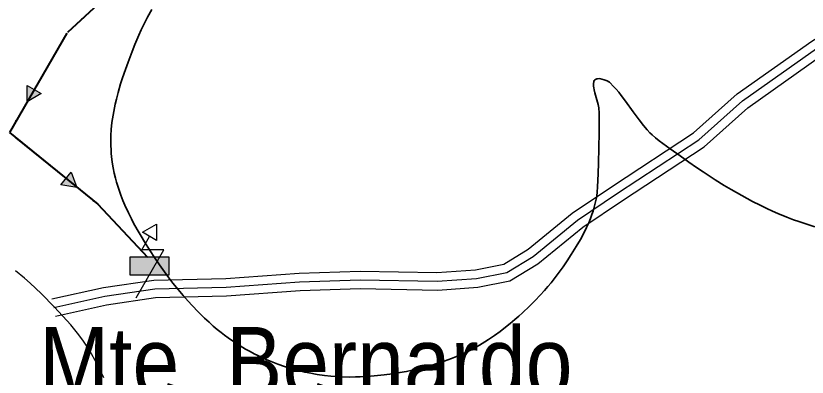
# Model space of a CAD drawing. Extents: x -64005 to -55000, y -89025 to -80000.
# Drawn here: x -61726 to -60821, y -88023 to -87610 of the extents above; entities that cross this region are included whole.
import ezdxf
from ezdxf.enums import TextEntityAlignment as Align

# ---------------------------------------------------------------- set-up
doc = ezdxf.new("R2010")
doc.units = 0
doc.header["$LTSCALE"] = 32
doc.linetypes.add('DOT_DASHED', pattern=[7.7, 5, -1.2, 0.3, -1.2])
doc.linetypes.add('LONG_DASHED', pattern=[7.5, 6, -1.5])
for name, color, linetype, lineweight in [('18', 7, 'Continuous', 25), ('24', 7, 'Continuous', 25), ('25', 7, 'Continuous', 35), ('39', 7, 'LONG_DASHED', 25), ('8', 7, 'Continuous', 25)]:
    doc.layers.add(name, color=color, linetype=linetype, lineweight=lineweight)
doc.layers.add('45', color=7, linetype='Continuous')

msp = doc.modelspace()

# ---------------------------------------------------------------- hatches: boundary and pattern name
at = {"layer": '18'}
for points in [[(-61696.9, -87699.17), (-61712.91, -87708.43), (-61712.93, -87689.93)], [(-61662.62, -87789.01), (-61656.02, -87806.29), (-61674.29, -87803.37)], [(-61595.69, -87906.11), (-61550.69, -87906.11), (-61550.69, -87886.11), (-61595.69, -87886.11)]]:
    msp.add_hatch(color=256, dxfattribs=at).paths.add_polyline_path(points)

# ---------------------------------------------------------------- linework, layer by layer
for p, q in [((-61667.98, -87630.44), (-61704.91, -87694.55)), ((-61725.87, -87749.53), (-61668.45, -87796.19)), ((-61618.97, -87839.71), (-61575.33, -87886.11))]:
    msp.add_line(p, q, dxfattribs=at)
at = {"layer": '18', "linetype": 'DOT_DASHED', "lineweight": 40}
msp.add_lwpolyline([(-62031.28, -86290.37), (-61300.5, -86486.3), (-61179.73, -86532.12), (-61069.18, -86626.02), (-60966.6, -86696.29), (-60858.8, -86771.78), (-60980.4, -86988.93), (-61117.47, -87235.6), (-61208.88, -87325.91), (-61262.1, -87419.12), (-61406.49, -87469.74), (-61549.57, -87520.74), (-61667.76, -87630.06), (-61733.17, -87743.6), (-61632.21, -87825.64), (-61575.32, -87886.11)], dxfattribs=at)
at = {"layer": '18'}
for points in [[(-61696.9, -87699.17), (-61712.91, -87708.43), (-61712.93, -87689.93)], [(-61662.62, -87789.01), (-61656.02, -87806.29), (-61674.29, -87803.37)], [(-61580.93, -87857.62), (-61564.91, -87848.36), (-61564.91, -87866.86)], [(-61595.69, -87906.11), (-61550.69, -87906.11), (-61550.69, -87886.11), (-61595.69, -87886.11)]]:
    msp.add_lwpolyline(points, close=True, dxfattribs=at)
msp.add_lwpolyline([(-61588.49, -87932.61), (-61556.8, -87877.61), (-61581.8, -87877.61), (-61572.92, -87862.24)], dxfattribs=at)
for centre in [(-61649.73, -87613.39), (-61725.39, -87730.09), (-61636.62, -87822.06)]:
    msp.add_circle(centre, 0.5, dxfattribs=at)
at = {"layer": '24'}
msp.add_lwpolyline([(-61625.47, -88023.89), (-61627.38, -88019.47), (-61633.41, -88007.54), (-61641.49, -87993.19), (-61649.48, -87980.82), (-61655.27, -87972.87), (-61663.12, -87963.26), (-61681.59, -87943.06), (-61696.95, -87927.52), (-61709.57, -87915.68), (-61716.11, -87910.02), (-61726.49, -87901.79)], dxfattribs=at)
at = {"layer": '25'}
for points in [[(-61587.11, -87854.54), (-61591.23, -87847.13), (-61593.85, -87842.16), (-61597.18, -87835.51), (-61601.3, -87826.55), (-61603.5, -87821.36), (-61605.84, -87815.36), (-61608.31, -87808.4), (-61610.84, -87800.28), (-61612.05, -87795.88), (-61613.49, -87789.94), (-61614.69, -87783.96), (-61615.37, -87779.95), (-61616.11, -87774.59), (-61616.83, -87767.41), (-61617.1, -87763.31), (-61617.29, -87758.62), (-61617.34, -87753.26), (-61617.2, -87747.15), (-61616.79, -87740.19), (-61615.98, -87732.31), (-61615.4, -87728.13), (-61613.97, -87719.6), (-61612.25, -87711.11), (-61610.94, -87705.47), (-61609, -87697.98), (-61606.09, -87688.02), (-61604.26, -87682.34), (-61602.03, -87675.86), (-61597.53, -87663.36), (-61592.91, -87651.05), (-61589.71, -87642.94), (-61585.23, -87632.26), (-61582.53, -87626.23), (-61579.3, -87619.41), (-61575.39, -87611.69), (-61570.61, -87602.99)], [(-61053.06, -87683.28), (-61055.75, -87682.52), (-61057.28, -87682.24), (-61058.96, -87682.08), (-61060.74, -87682.13), (-61061.61, -87682.28), (-61062.45, -87682.53), (-61063.24, -87682.91), (-61063.95, -87683.45), (-61064.52, -87684.2), (-61064.89, -87685.2), (-61065.28, -87687.93), (-61065.31, -87690.66), (-61065.16, -87692.5), (-61064.78, -87694.95), (-61064.03, -87698.23), (-61060.14, -87711.47), (-61059.38, -87715.28), (-61059.13, -87717.32), (-61059.03, -87719.49), (-61058.99, -87731.62), (-61059.03, -87743.75), (-61059.24, -87761.27), (-61059.61, -87778.8), (-61059.99, -87790.48), (-61060.69, -87806.06), (-61061.1, -87811.26), (-61061.78, -87816.41), (-61062.38, -87819.81), (-61063.34, -87824.31), (-61064.9, -87830.24), (-61065.93, -87833.61), (-61067.22, -87837.42), (-61068.84, -87841.75), (-61070.86, -87846.67), (-61073.38, -87852.23), (-61076.5, -87858.54), (-61080.36, -87865.7), (-61085.07, -87873.81), (-61090.77, -87883.01), (-61095.46, -87890.19), (-61100.25, -87897.15), (-61103.51, -87901.68), (-61107.93, -87907.58), (-61113.97, -87915.21), (-61117.5, -87919.45), (-61121.61, -87924.21), (-61126.41, -87929.54), (-61132.04, -87935.48), (-61138.66, -87942.09), (-61146.5, -87949.46), (-61150.8, -87953.3), (-61155.48, -87957.35), (-61160.59, -87961.61), (-61166.17, -87966.1), (-61172.27, -87970.83), (-61178.78, -87975.61), (-61185.33, -87980.08), (-61189.73, -87982.9), (-61195.66, -87986.47), (-61203.72, -87990.92)], [(-60812.39, -87851.2), (-60821.64, -87848.44), (-60830.69, -87845.45), (-60836.63, -87843.32), (-60844.46, -87840.33), (-60854.76, -87836.05), (-60860.59, -87833.47), (-60867.23, -87830.4), (-60874.8, -87826.73), (-60883.45, -87822.35), (-60895.79, -87815.72), (-60907.89, -87808.81), (-60915.83, -87804.06), (-60926.27, -87797.56), (-60939.98, -87788.63), (-60947.71, -87783.42), (-60956.48, -87777.38), (-60966.41, -87770.38), (-60977.68, -87762.28), (-60990.47, -87752.94), (-60994.54, -87749.74), (-60998.4, -87746.28), (-61000.87, -87743.84), (-61004.06, -87740.46), (-61008.14, -87735.74), (-61013.33, -87729.15), (-61019.97, -87720.07), (-61028.65, -87707.9), (-61033.7, -87701.17), (-61036.46, -87697.71), (-61039.48, -87694.15), (-61042.81, -87690.52), (-61046.5, -87686.87), (-61047.17, -87686.3), (-61047.95, -87685.74), (-61049.76, -87684.68), (-61051.12, -87684.03), (-61053.06, -87683.28)], [(-61203.72, -87990.92), (-61208.42, -87993.31), (-61213.9, -87995.91), (-61220.31, -87998.74), (-61227.86, -88001.78), (-61236.14, -88004.82), (-61244.44, -88007.59), (-61249.98, -88009.29), (-61257.38, -88011.37), (-61267.26, -88013.85), (-61272.91, -88015.13), (-61279.38, -88016.45), (-61286.78, -88017.81), (-61295.26, -88019.17), (-61304.96, -88020.47), (-61316.06, -88021.67), (-61324.05, -88022.3), (-61332.07, -88022.72), (-61337.44, -88022.87), (-61344.61, -88022.9), (-61354.19, -88022.64), (-61359.67, -88022.34), (-61365.93, -88021.84), (-61373.1, -88021.08), (-61381.28, -88019.94), (-61390.62, -88018.29), (-61395.6, -88017.25), (-61400.89, -88016.02), (-61406.53, -88014.56), (-61412.52, -88012.84), (-61418.9, -88010.81), (-61426.51, -88008.13), (-61433.95, -88005.25), (-61438.81, -88003.22), (-61445.18, -88000.37), (-61453.48, -87996.31), (-61458.13, -87993.85), (-61463.37, -87990.92), (-61469.26, -87987.41), (-61475.86, -87983.17), (-61483.26, -87978.03), (-61487.15, -87975.16), (-61491.25, -87971.99), (-61495.57, -87968.5), (-61500.14, -87964.64), (-61504.95, -87960.36), (-61510.03, -87955.62), (-61517.35, -87948.42), (-61524.36, -87941.15), (-61528.87, -87936.27), (-61534.7, -87929.69), (-61542.16, -87920.81), (-61546.28, -87915.66), (-61550.88, -87909.71), (-61556.01, -87902.81), (-61561.71, -87894.79), (-61568.05, -87885.43), (-61575.13, -87874.44), (-61578.85, -87868.45), (-61582.78, -87861.95), (-61587.11, -87854.54)]]:
    msp.add_lwpolyline(points, dxfattribs=at)
at = {"layer": '39'}
msp.add_lwpolyline([(-61682.66, -87943.49), (-61624.01, -87930.45), (-61567.15, -87922.15), (-61485.4, -87920.36), (-61401.54, -87914.21), (-61332.23, -87911.83), (-61243.98, -87913.59), (-61199.1, -87910.35), (-61164.6, -87903.51), (-61134.57, -87885.35), (-61083.65, -87843.86), (-61038.04, -87813.03), (-60945.03, -87751.99), (-60894.96, -87707.29), (-60810.36, -87647.49), (-60702.44, -87581.03), (-60641.06, -87527.36), (-60578.51, -87467.48), (-60546.87, -87444.97), (-60520.46, -87425.15)], dxfattribs=at)
at = {"layer": '8', "linetype": 'LONG_DASHED'}
msp.add_lwpolyline([(-61684.83, -87933.73), (-61625.82, -87920.61), (-61567.98, -87912.17), (-61485.87, -87910.37), (-61402.08, -87904.22), (-61332.3, -87901.83), (-61244.51, -87903.58), (-61200.44, -87900.42), (-61167.96, -87893.86), (-61140.17, -87877.05), (-61089.63, -87835.82), (-61043.79, -87804.84), (-60951.14, -87744.04), (-60901.06, -87699.33), (-60815.87, -87639.14), (-60708.5, -87573.05), (-60647.63, -87519.82), (-60584.9, -87459.75), (-60553.22, -87437.23), (-60532.74, -87421.86)], dxfattribs=at)
at = {"layer": '8'}
msp.add_lwpolyline([(-61680.49, -87953.25), (-61622.2, -87940.29), (-61566.32, -87932.13), (-61484.93, -87930.35), (-61401, -87924.2), (-61332.16, -87921.83), (-61243.45, -87923.6), (-61197.76, -87920.28), (-61161.24, -87913.16), (-61128.97, -87893.65), (-61077.68, -87851.9), (-61032.29, -87821.22), (-60938.92, -87759.94), (-60888.86, -87715.25), (-60804.85, -87655.84), (-60696.38, -87589.01), (-60634.49, -87534.9), (-60572.12, -87475.21), (-60540.52, -87452.71), (-60526.59, -87442.26)], dxfattribs=at)

# ---------------------------------------------------------------- texts
at = {"layer": '45', "width": 0.9}
msp.add_text('Mte. Bernardo', height=80, rotation=0.008, dxfattribs=at).set_placement((-61394.46, -88045.7), align=Align.CENTER)

doc.saveas('drawing.dxf')
